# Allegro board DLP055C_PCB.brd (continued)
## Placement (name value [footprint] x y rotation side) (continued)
TP150  TP_WHT  [TP_KEYSTONE_5011]  133.67 69.22 0 top
TP151  TP_WHT  [TP_KEYSTONE_5011]  129.22 69.22 0 top
TP153  TP_WHT  [TP_KEYSTONE_5011]  124.14 55.25 0 top
TP154  TP_WHT  [TP_KEYSTONE_5011]  127.95 55.25 0 top
TP155  TP_WHT  [TP_KEYSTONE_5011]  136.84 66.04 0 top
TP156  TP_WHT  [TP_KEYSTONE_5011]  125.41 69.22 0 top
TP159  TP,28mil Drill,48mil Pad  [HTP-48RD28]  174.31 84.45 0 top
TP163  TP_WHT  [TP_KEYSTONE_5011]  106.36 61.59 0 top
TP164  TP_WHT  [TP_KEYSTONE_5011]  106.36 66.04 270 top
TP165  TP_WHT  [TP_KEYSTONE_5011]  112.87 61.45 270 top
TP166  TP_WHT  [TP_KEYSTONE_5011]  117.16 61.59 270 top
TP167  TP_WHT  [TP_KEYSTONE_5011]  104.14 73.34 270 top
TP168  TP_WHT  [TP_KEYSTONE_5011]  121.6 61.59 270 top
TP169  TP_WHT  [TP_KEYSTONE_5011]  106.05 69.85 0 top
TP170  TP_WHT  [TP_KEYSTONE_5011]  113.98 74.93 270 top
TP208  TP_WHT  [TP_KEYSTONE_5011]  119.06 34.29 0 top
TP209  HDR,1P,1R  [HDR1]  142.56 31.75 0 top
TP210  TP_WHT  [TP_KEYSTONE_5011]  137.48 38.73 0 top
TP211  HDR,1P,1R  [HDR1]  148.91 31.75 0 top
TP212  TP,28mil Drill,48mil Pad  [HTP-48RD28]  115.89 20.95 0 top
TP213  TP,28mil Drill,48mil Pad  [HTP-48RD28]  68.9 10.79 0 top
TP214  TP,28mil Drill,48mil Pad  [HTP-48RD28]  73.34 10.79 0 top
TP215  TP,28mil Drill,48mil Pad  [HTP-48RD28]  46.04 10.16 0 top
TP216  TP,28mil Drill,48mil Pad  [HTP-48RD28]  47.94 10.16 0 top
TP217  TP,20mil PAD  [20MIL_PAD]  146.69 60.96 0 top
TP218  TP,28mil Drill,48mil Pad  [HTP-48RD28]  110.81 73.98 0 top
TP219  TP,28mil Drill,48mil Pad  [HTP-48RD28]  148.27 63.5 0 top
TP220  TP,28mil Drill,48mil Pad  [HTP-48RD28]  152.72 62.86 0 top
TP227  Testpoint_via  [TP-30RD12]  91.36 43.42 270 top
TP228  Testpoint_via  [TP-30RD12]  74.77 59.01 270 top
TP229  Testpoint_via  [TP-30RD12]  87.3 55.46 270 top
TP230  Testpoint_via  [TP-30RD12]  75.36 64.12 270 top
TP231  Testpoint_via  [TP-30RD12]  86.91 65.01 0 top
TP232  Testpoint_via  [TP-30RD12]  83.1 33.89 0 top
TP233  Testpoint_via  [TP-30RD12]  52.86 85.56 180 top
TP234  Testpoint_via  [TP-30RD12]  70.96 51.01 270 top
TP235  Testpoint_via  [TP-30RD12]  63.55 70.21 0 top
TP236  Testpoint_via  [TP-30RD12]  60.64 60.96 0 top
TP237  Testpoint_via  [TP-30RD12]  72.46 64.25 180 top
TP238  Testpoint_via  [TP-30RD12]  73.98 63.5 0 top
TP239  Testpoint_via  [TP-30RD12]  77.21 64.8 180 top
TP240  Testpoint_via  [TP-30RD12]  62.55 64.77 0 top
TP241  Testpoint_via  [TP-30RD12]  55.56 63.5 0 top
TP242  Testpoint_via  [TP-30RD12]  12.38 52.07 0 top
TP243  Testpoint_via  [TP-30RD12]  50.48 93.34 0 top
TP244  Testpoint_via  [TP-30RD12]  52.27 133.38 0 top
TP245  Testpoint_via  [TP-30RD12]  66.99 119.38 0 top
TP246  Testpoint_via  [TP-30RD12]  61.91 132.08 0 top
TP247  Testpoint_via  [TP-30RD12]  77.69 139.93 0 top
TP248  Testpoint_via  [TP-30RD12]  167.96 133.98 0 top
TP249  Testpoint_via  [TP-30RD12]  49.6 35.65 0 top
TP263  Testpoint  [TP-48RD28]  167.96 17.14 180 top
TP264  Testpoint  [TP-48RD28]  177.72 30.08 180 top
TP265  TP,20mil PAD  [20MIL_PAD]  28.26 127 90 top
TP266  TP,20mil PAD  [20MIL_PAD]  26.35 127 90 top
TP267  TP,20mil PAD  [20MIL_PAD]  24.45 127 90 top
TP268  TP_WHT  [TP_KEYSTONE_5011]  180.66 12.7 0 top
TP269  TP_WHT  [TP_KEYSTONE_5011]  171.77 14.61 0 top
TP270  TP_WHT  [TP_KEYSTONE_5011]  176.21 14.61 0 top
TP271  TP_WHT  [TP_KEYSTONE_5011]  184.47 10.16 0 top
TP272  Testpoint_via  [TP-30RD12]  45.64 59.93 0 top
TP273  Testpoint_via  [TP-30RD12]  41.4 49.64 0 top
TP274  Testpoint_via  [TP-30RD12]  44.13 48.89 0 top
TP275  Testpoint_via  [TP-30RD12]  44.13 46.35 0 top
TP276  Testpoint_via  [TP-30RD12]  12.38 53.97 0 top
TP277  Testpoint_via  [TP-30RD12]  51.75 91.44 0 top
TP278  Testpoint_via  [TP-30RD12]  128.37 119.85 0 top
TP279  Testpoint_via  [TP-30RD12]  131.13 131.44 0 top
TP280  Testpoint_via  [TP-30RD12]  103.19 123.83 0 top
TP281  Testpoint_via  [TP-30RD12]  94.3 123.19 0 top
TP282  Testpoint_via  [TP-30RD12]  152.63 112.13 0 top
TP283  Testpoint_via  [TP-30RD12]  131.76 105.41 0 top
TP284  TP,28mil Drill,48mil Pad  [HTP-48RD28]  174.62 95.39 90 top
TP285  TP,28mil Drill,48mil Pad  [HTP-48RD28]  178.48 75.24 90 top
TP286  TP,28mil Drill,48mil Pad  [HTP-48RD28]  85.24 144.84 90 top
U1  TPD2E2U06DRL  [SOT-5_DRL_R-PDSO-N5]  82.23 143.51 90 top
U2  74AHC1G32  [SOIC5-SOT-23_DBV-TI]  63.82 138.11 90 top
U3  74AHC1G08  [SOIC5-SOT-23_DBV-TI]  73.66 138.11 90 top
U4  MT28EW128ABA1HJS-0SIT  [SOIC56-TSOP_SPANSION]  152.08 138.43 180 top
U7  TPS2501DRCR  [TI_DRC0010J_VSON-10]  87.46 125.89 0 top
U8  MT28EW128ABA1HJS-0SIT  [SOIC56-TSOP_SPANSION]  152.08 120.33 180 top
U9  TSOP34838  [SOIC5-SOT-23_DBV-TI]  174.31 26.67 0 bottom
U11  SN74LVC1G17DBVR  [SOIC5-SOT-23_DBV-TI]  167.32 19.68 270 bottom
U12  SN74AUP1G07DCK  [U_5_DCK]  177.8 90.8 180 top
U13  SN74AUP1G07DCK  [U_5_DCK]  90.49 28.89 90 top
U14  SN74AUP1G06DCK  [U_5_DCK]  96.52 39.05 90 top
U15  TIDLP,DLPC7540  [DLPC7540_HBGA676_3131]  151.45 88.9 90 top
U16  SN74AUP1G07DCK  [U_5_DCK]  177.8 86.36 180 top
U17  TPD2E001DRY  [SOIC6-DRY_TI]  11.11 93.98 270 top
U18  SN74AUP1G07DCK  [U_5_DCK]  84.14 29.21 90 top
U19  SN74AUP1G06DCK  [U_5_DCK]  96.52 34.92 90 top
U20  SN74AUP1G07DCK  [U_5_DCK]  96.52 30.8 90 top
U26  MSP430F5529IPN  [PQFP80-PN_TI]  25.72 116.2 180 top
U27  TXS0102  [VSSOP-8_DCU]  37.78 73.03 270 top
U30  AT24C64D-SSHM-T  [SOIC8]  105.73 50.16 0 top
U32  TPS56C230  [20VQFN-HR_RJE]  160.99 53.97 0 top
U33  SN74LVC1G06DBVR  [SOIC5-SOT-23_DBV-TI]  165.12 50.48 270 top
U34  TXS0102  [VSSOP-8_DCU]  172.4 44.77 270 top
U35  DRV8847  [16HTSSOP_PWP0016C]  148.27 43.5 180 top
U36  TXS0102  [VSSOP-8_DCU]  120.33 4.45 180 bottom
U37  TXS0102  [VSSOP-8_DCU]  123.51 4.45 180 bottom
U38  SN74AHC1G125DBVR  [SOIC5-SOT-23_DBV-TI]  71.44 13.97 0 top
U39  SN74LVC1G07DBVR  [SOIC5-SOT-23_DBV-TI]  77.79 13.97 0 top
U40  SN74AUP1G07DCK  [U_5_DCK]  43.81 87.63 270 top
U42  SN74AUP1G07DCK  [U_5_DCK]  44.13 91.44 270 top
U43  SN74LVC827APWR  [SOIC24-PW_TI]  129.86 61.59 180 top
U46  MAX3232CPWR  [SOIC16-PW_TI]  15.88 31.75 90 top
U47  TSOP34838  [SOIC5-SOT-23_DBV-TI]  141.29 57.78 270 top
U48  SN74LVC1G06DBVR  [SOIC5-SOT-23_DBV-TI]  101.28 66.04 270 bottom
U49  SN74LVC827APWR  [SOIC24-PW_TI]  113.35 67.94 180 top
U51  74LVTH16244  [SOIC48-DGG_TI]  127.95 34.92 0 top
U53  TSOP34838  [IR3-TSOP34_VIS]  115.25 85.09 0 top
U54  TSOP34838  [IR3-TSOP34_VIS]  105.73 85.09 0 top
U55  74AHC1G32  [SOIC5-SOT-23_DBV-TI]  137.48 33.66 0 top
U58  SN74LVC1G17DBVR  [SOIC5-DBV_TI]  81.6 107.95 90 bottom
U59  TPS259260DRCR  [SOIC10-DRC_TI]  62.55 123.83 180 bottom
U500  38MHz  [SIT1602BC-13-2520_CTS_SITIME]  131.13 93.34 270 bottom
U501  TPD2E2U06DRL  [SOT-5_DRL_R-PDSO-N5]  19.37 76.83 90 top
U502  40MHz  [OSC4-KC2520B_KYO]  180.02 94.61 180 bottom
U503  CDCLVC1102PW  [SOIC8-PW_TI]  176.21 90.8 270 bottom
U519  N-CHANNEL MOSFET  [SOT323_DIODESINC]  77.15 143.51 180 top
U520  SN74LVC1G07  [SOIC5-SOT-23_DBV-TI]  77.15 144.14 180 bottom
U521  TPS259241  [SOIC10-DRC_TI]  63.18 127 90 top
U522  CSD17579  [SOIC8-Q5_TI]  68.9 132.08 0 top
U523  N-CHANNEL MOSFET  [SOT23AVX]  83.38 91.44 90 bottom
U524  TPS54327  [SOIC8-DDA-A_TI]  166.05 140.34 180 bottom
U525  LM3881  [SOIC8-DGK_TI]  87.31 96.52 270 top
U526  LM3881  [SOIC8-DGK_TI]  84.77 91.44 270 top
U527  N-CHANNEL MOSFET  [SOT23AVX]  91.12 90.8 90 top
U528  N-CHANNEL MOSFET  [SOT23AVX]  91.12 90.17 180 bottom
U529  SN74LVC1G07  [SOIC5-SOT-23_DBV-TI]  86.04 109.86 270 bottom
U538  LM393  [SOIC8-PW_TI]  126.05 121.92 0 bottom
U539  LM393  [SOIC8-PW_TI]  134.3 109.86 90 bottom
U555  (MOTOR DRIVE)  [QF48_PPAD-A]  67.63 59.05 0 top
U556  (MOTOR DRIVE)  [QF48_PPAD-A]  28.26 51.44 0 top
U557  (MOTOR DRIVE)  [QF48_PPAD-A]  76.52 100.97 0 top
U558  SN74AUP1G07DCK  [U_5_DCK]  25.32 116.44 90 bottom
U559  TXS0102  [VSSOP-8_DCU]  16.83 100.97 0 top
U560  M24C64-WMN6TP  [SOIC8-D_TI]  37.78 78.11 90 top
U561  TXS0102  [VSSOP-8_DCU]  36.51 83.82 90 top
U562  CY7C65215A-32LTXI  [QFN32-5X5-A_CYP]  25.08 78.11 270 top
U563  SN74AUP1G06DCK  [U_5_DCK]  31.43 80.64 90 top
U564  SN74AUP1G06DCK  [U_5_DCK]  44.13 83.82 270 top
U565  74AHC1G32  [SOIC5-SOT-23_DBV-TI]  60.01 146.05 0 top
U566  LM393  [SOIC8-PW_TI]  98.74 119.38 180 bottom
U567  TSOP34838  [SOIC5-SOT-23_DBV-TI]  179.39 26.04 0 bottom
U568  SN74LVC1G07  [SOIC5-SOT-23_DBV-TI]  65.5 147.79 180 bottom
U569  SN74LVC1G07  [SOIC5-SOT-23_DBV-TI]  69.41 147.76 180 bottom
VR1  20K  [POT-3314G]  127.32 127.64 0 top
VR2  20K  [POT-3314G]  98.74 127 270 top
VR3  20K  [POT-3314G]  134.94 109.86 270 top
X1  40 MHz  [TXC_TM3225]  172.72 92.39 270 top
X2  38 MHz  [TXC_TM3225]  131.44 88.27 90 bottom

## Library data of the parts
C1 C2 C5-C8 C10 C15 C27 C34 C71 C74 C91 C95-C97 C108-C110 C126 C127 C130 C133 C136 C137 C141 C147 C161 C170 C172 C202 C240 C242 C259 C557 C576 C583 C668 C669 C677-C679 C697-C699 = PAS,CAP,NP
C14 C69 C70 C124 C125 C134 C135 C138 C148-C160 C162-C169 C171 C173-C201 C203-C239 C241 C243-C258 C260-C269 C275-C291 C298-C304 C317 C320 C321 C502-C504 C507 C508 C511 C514 C515 C517 C528-C530 C547 C548 C622-C625 C654 C664-C667 C670 C675 C676 C682-C684 C687-C696 C700 C830 C837 = PAS,CAP,NP: alternate symbols: (0402_1mm)
C18 C60 C752-C759 C762-C801 C806-C808 C810-C820 C827-C829 C831-C836 = C
C49-C54 C61-C68 C72 C73 = CER 0.1UF 16V 10% X5R 0402: alternate symbols: (0402_1mm); signal model: CER_0.1UF_16V_10%_X5R_0402_0402_100nF
C58 C59 C760 C761 C802-C805 C821-C826 = CAPACITOR_POL
C519-C521 C531 C549 C585 = CER 0.1UF 16V 10% X5R 0402: alternate symbols: (0402_1mm)
C809 = CAP NP: alternate symbols: (0603)
D1 D5-D8 D10 D15 D52 D53 = PAS,DIODE,LED,ALT
D30 D32 D35-D48 = Schottky_Diode
D49 D51 = PAS,DIODE,ZENOR,SOT-23,Ap1,Cp3
D50 = PWR,REF,LMV431A,SOT-23
DN1-DN12 = DS_DUAL_S_AJK
F1 = PAS,FERRITE BEAD,3
FB1-FB4 = Ferrite Bead_1
J2 = EM,CONN,USB,TYPE-AB
J3 J7 J10 = TMP_154138
J4 J5 J8 J11 J62 = EM,HDR,2P,1R,1x,B2B_EH,inline
J6 = EM,HDR,10P,1R
J9 J26 J52-J57 J60 J61 J67 J68 J72 J84 J94 J95 J98 J530 = EM,JMP,2P,1R
J12 J16 J536 = EM,HDR,4P,1R,1x,picoblade
J14 J15 = HDR_2: alternate symbols: (HDR2_2MM)
J17 = EM,CONN,12P+2G,1R,FLEX,1x
J20 J21 J27 = EM,HDR,6P,1R
J22 J23 J45 J103-J105 J506 = EM,HDR,6P,1R,1x,B6B-EH
J28 J115 = EM,HDR,12P,1R
J42 J44 J500 = EM,CONN,51P,FI-RE51S,VF and HF
J43 J69 J110 = EM,HDR,14P,1R
J51 = EM,CONN,4P,EH,Devasys,1x
J64 J76 J78 J82 J86 J87 J89 J106 J502 J505 = EM,JMP,3P,1R,1X,ALT
J70 = EM,HDR,14P,2R,1X,Narrow
J73 J503 = EM,HDR,4P,1R,1x,B4B-EH
J74 = EM,HDR,4P,1R,1x,NARROW
J75 = EM,JMP,10P,2R,1x
J77 J79 J88 J90 = EM,JMP,1P,1R,2
J83 = EM,CONN,USB,TYPE-B
J85 = EM,HDR,3P,1R,1x,B3B-EH
J96 = EM,HDR,12P,1R,1x
J97 = EM,HDR,22P,2R
J102 = EM,CONN,DB9,ALT
J111-J113 = EM,HDR,6P,2R,1x
J114 = EM,HDR,3P,1R
J120 J121 = EM,HDR,12P,1R,1x,B12B-EH
J122 = EM,HDR,7P,1R,1x,B7B-EH
J501 = EM,HDR,20P,2R,NARROW_SYM
J515 J519 J523 = CON4_0
J516-J518 J520-J522 J524-J526 = 2pin
J527 J528 = EM,HDR,2P,1R,2x
J529 = PJ-002AH_0
J532 J533 J535 = CON3_0
L2 L11 = PAS,INDUCTOR
L13-L24 L505 L506 = PAS,INDUCTOR: alternate symbols: (0402_1mm)
L515-L531 = L
Q1 = ANA,TRANSISTOR,2N2222A,SOT-23
Q6 = ANA,MOSFET,N-CH,E,3PICOSTAR_0
Q10 = NTD14NO3RT4_1
Q11 = NTD14N03RT4G_CUS
Q12 = ANA,MOSFET,P-CH,E,SOT223
Q13 = ANA,MOSFET,N-CH,E,2N7002,SOT-23
R1 R2 R8-R11 R13 R14 R18-R22 R29-R31 R34 R36 R38-R40 R43 R51-R53 R55-R57 R61 R63 R64 R73 R75-R79 R81-R83 R87 R88 R90 R91 R95-R97 R99-R101 R103-R106 R109-R114 R116-R125 R127 R128 R133-R151 R153-R157 R168 R169 R200 R201 R209-R212 R217 R219 R222 R234 R235 R237 R256-R261 R504-R508 R511 R517 R519 R520 R522-R526 R528 R529 R533-R540 R542-R550 R581 R585 R586 R589 R590 R592-R599 R601 R604-R615 R623 R626-R629 R632 R635 R640 R642-R656 R660-R680 R706 R710-R717 R853-R855 R859-R871 R884-R887 = PAS,R,large: alternate symbols: (0402_1mm)
R4 R5 = PAS,R,large: signal model: PAS_R_LARGE_0402_27.4__27.4
R32 R37 R42 R54 R62 R65 R66 R80 R84-R86 R89 R92-R94 R98 R102 R152 R218 R226 R246 R856-R858 = PAS,R,large
R108 R175 R176 R179 R181 R184 R193 R195-R198 R739 R740 R742 R744 R747 R750-R752 R754-R756 R758 R759 R763-R821 R827 R828 R830 R832-R834 R836 R838 R840-R852 R872-R883 = R
R822-R826 R829 R839 = PAS,R
R831 R835 R837 = R: alternate symbols: (0402-1MM)
SW1 SW3 = EM,SW,SPDT,GT11,1x
SW5 = SW SPST_1: alternate symbols: (SW5_GT12MSCBE)
TP1-TP3 TP5-TP9 TP11 TP12 TP14 TP20-TP24 TP38-TP40 TP46-TP56 TP78-TP89 TP106-TP109 TP129-TP141 TP144-TP151 TP153-TP156 TP159 TP163-TP170 TP208-TP220 TP268-TP271 TP284-TP286 = EM,TERM,TESTPOINT
TP32-TP37 TP41-TP43 TP64-TP77 TP111-TP128 TP265-TP267 = BF,HOLE,PLATED,TESTPIN
TP227-TP249 TP272-TP283 = Testpoint
TP263 TP264 = EM,TERM,TESTPOINT: alternate symbols: (TP-48RD28)
U1 U501 = PAS,DIODE,TVS,TPD2E2U06DRL,1x
U2 U55 U565 = LOG,OR,Tiny Logic,small
U3 = LOG,AND,Tiny Logic,Small
U4 U8 = MEM,FLASH,256Mb,x16,TSOP-56
U7 = PWR,SW,TPS2501,USB
U9 U38 U47 U567 = LOG,BUF,74LVC1G125,1x
U11 = LOG,BUF,SCHMITT_TRIG,1G17_7
U12 = TMP_18
U13 = TMP_21
U14 = TMP_22
U15 = TIDLP,DLPC7540
U16 = TMP_4
U17 = PAS,DIODE,TVS,TPD2E001DRY,1x
U18 = TMP_20
U19 = TMP_19
U20 = TMP_23
U26 = PROC,MICCNTL,1x,MSP430F5529IPN
U27 U34 U36 U37 U559 U561 = INF,DRVR,I2C,TXS0102,1x
U30 = MEM,EEPROM,24LCxx,ALT
U32 = PWR,REG,TPS56C230,1X
U33 = TMP_24
U35 = ANA,DRV,DRV8447,1x_3
U39 = TMP_30
U40 = TMP_27
U42 = TMP_28
U43 U49 = LOG,BUF,74X827A
U46 = INF,DRVR,RS232,MAX3232E
U48 = TMP_31
U51 = LOG,BUF,74x16244
U53 U54 = ANA,LIGHTSENSOR,IR_RECVR
U58 = LOG,BUF,SCHMITT_TRIG,1G17_8
U59 = TPS259260
U500 U502 = ANA,OSC,4P,1X,small
U503 = INF,CLK DRVR,CDCLVC1102
U519 U523 U527 U528 = N-FET
U520 U568 U569 = TMP_33
U521 = TPS259240_0
U522 = CSD17579
U524 = TPS54327_0
U525 U526 = LM3881
U529 = TMP_32
U538 U539 U566 = OPAMP_DUAL
U555 = PMD1000_2
U556 U557 = PMD1000_3
U558 = TMP_29
U560 = MEM,EEPROM,24LCxx
U562 = INF,USB2SERIAL,CY7C65215,1x
U563 = TMP_25
U564 = TMP_26
VR1-VR3 = POT_R_S
X1 = 7V-40.000MDDE-T_CUS
X2 = 7V-38.000MAAV-T_CUS

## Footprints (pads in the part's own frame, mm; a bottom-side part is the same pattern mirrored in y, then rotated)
3-PICOSTAR_3-XFDFN
  rect 0.222x0.35 smd: 1(-0.175,-0.325) 2(0.175,-0.325)
  rect 0.6x0.35 smd: 3(0,0.325)
16HTSSOP_PWP0016C
  rect 1.5x0.45 smd: 1(-2.9,2.275) 2(-2.9,1.625) 3(-2.9,0.975) 4(-2.9,0.325) 5(-2.9,-0.325) 6(-2.9,-0.975) 7(-2.9,-1.625) 8(-2.9,-2.275) 9(2.9,-2.275) 10(2.9,-1.625) 11(2.9,-0.975) 12(2.9,-0.325) 13(2.9,0.325) 14(2.9,0.975) 15(2.9,1.625) 16(2.9,2.275)
  rect 2.46x2.31 smd: 17(0,0)
20MIL_PAD
  round 0.508 smd: 1(0,0)
20VQFN-HR_RJE
  rect 0.6x0.2 smd: 1(-1.4,0.9) 2(-1.4,0.45) 3(-1.4,0) 4(-1.4,-0.45) 5(-1.4,-0.9) 11(1.4,-0.9) 12(1.4,-0.45) 13(1.4,0) 14(1.4,0.45) 15(1.4,0.9)
  rect 0.2x0.6 smd: 6(-0.9,-1.4) 7(-0.45,-1.4) 8(0,-1.4) 9(0.45,-1.4) 10(0.9,-1.4) 16(0.9,1.4) 17(0.45,1.4) 18(0,1.4) 19(-0.45,1.4) 20(-0.9,1.4)
  rect 0.926x0.975 smd: 21(0.123,-0.007)
35F0121-1SR-10_LAIRD
  rect 2.769x1.473 smd: 1(-4.013,0) 2(4.013,0)
0201
  rect 0.356x0.305 smd: 1(-0.305,0) 2(0.305,0)
0402
  rect 0.5x0.5 smd: 1(-0.521,0) 2(0.521,0)
0603
  rect 0.762x1.016 smd: 1(0.838,0) 2(-0.838,0)
0805
  rect 1.295x1.499 smd: 1(-0.95,0) 2(0.95,0)
0805WIDE-KRL2012E_SUSUMU
  rect 2.311x0.787 smd: 1(0,0.61) 2(0,-0.61)
1206
  rect 1.6x1.6 smd: 1(-1.397,0) 2(1.397,0)
1210
  rect 0.9x2.3 smd: 1(-1.55,0) 2(1.55,0)
7343
  rect 2.591x2.388 smd: 1(-3.2,0) 2(3.2,0)
COILCRAFT_LPS4018
  rect 1.905x4.572 smd: 1(-1.587,0) 2(1.587,0)
CONN2-B2B-EH_JST
  rect 1.575x1.575 hole 1.067: 1(0,0)
  round 1.575 hole 1.067: 2(2.489,0)
CONN3-53398-A_MOLEX
  rect 2.108x2.997 smd: (-3.8,-2.913) (3.8,-2.913)
  rect 0.61x1.6 smd: 1(-1.25,0) 2(0,0) 3(1.25,0)
CONN3-B3B-EH_JST
  rect 1.575x1.575 hole 1.067: 1(0,0)
  round 1.575 hole 1.067: 2(-2.489,0) 3(-4.978,0)
CONN4-52808_MOLEX
  rect 0.61x1.448 smd: 1(-1.501,-1.778) 3(0.5,-1.778)
  rect 0.61x1.651 smd: 2(-0.5,1.778) 4(1.501,1.778)
CONN4-53398_MOLEX
  rect 2.1x3 smd: (-4.425,-2.75) (4.425,-2.75)
  rect 0.8x1.3 smd: 1(-1.875,0) 2(-0.625,0) 3(0.625,0) 4(1.875,0)
CONN4-S4BEH_JST
  rect 1.575x1.575 hole 1.067: 1(0,0)
  round 1.575 hole 1.067: 2(2.489,0) 3(4.978,0) 4(7.468,0)
CONN4-USB-897-43-004-90_MILL
  round 1.422 hole 0.914: 1(0,0) 2(-2.5,0) 3(-2.5,-2) 4(0,-2)
  round 3.175 hole 2.286: 5(4.77,-4.71) 6(-7.27,-4.71)
CONN6-53398-0690_MOLEX
  rect 2.108x2.997 smd: (-5.675,-1.85) (5.675,-1.85)
  rect 0.61x1.6 smd: 1(-3.125,1.063) 2(-1.875,1.063) 3(-0.625,1.063) 4(0.625,1.063) 5(1.875,1.063) 6(3.125,1.063)
CONN9-190-009-A_NORCOMP_REV
  round 4.216 hole 3.2: (-12.495,-0.65) (12.495,-0.65)
  round 0.762 hole 1.499 unplated: (-7.95,-0.65) (7.95,-0.65)
  rect 0.787x3.708 smd: 1(-5.54,0) 2(-2.77,0) 3(0,0) 4(2.77,0) 5(5.54,0) 6(-4.155,0) 7(-1.385,0) 8(1.385,0) 9(4.155,0)
CONN12-53398_MOLEX
  rect 2.108x2.997 smd: (-9.425,-1.85) (9.425,-1.85)
  rect 0.61x1.6 smd: 1(-6.875,1.063) 2(-5.625,1.063) 3(-4.375,1.063) 4(-3.125,1.063) 5(-1.875,1.063) 6(-0.625,1.063) 7(0.625,1.063) 8(1.875,1.063) 9(3.125,1.063) 10(4.375,1.063) 11(5.625,1.063) 12(6.875,1.063)
CONN12-FH12_HRS
  rect 1.854x2.184 smd: (-4.5,-2.895) (4.5,-2.895)
  rect 0.254x1.016 smd: 1(-2.75,0) 2(-2.25,0) 3(-1.75,0) 4(-1.25,0) 5(-0.75,0) 6(-0.25,0) 7(0.25,0) 8(0.75,0) 9(1.25,0) 10(1.75,0) 11(2.25,0) 12(2.75,0)
CONN14-XF2M-REV-A_OMRON
  rect 1.905x1.524 smd: (-5.201,-3.987) (5.201,-3.987)
  rect 0.254x1.295 smd: 1(3.25,0) 2(2.75,0) 3(2.25,0) 4(1.75,0) 5(1.25,0) 6(0.75,0) 7(0.25,0) 8(-0.25,0) 9(-0.75,0) 10(-1.25,0) 11(-1.75,0) 12(-2.25,0) 13(-2.75,0) 14(-3.25,0)
CONN22-B22B-PHD_JST
  rect 1.473x1.473 hole 0.965: 1(0,0)
  round 1.473 hole 0.965: 2(2,0) 3(0,2) 4(2,2) 5(0,4) 6(2,4) 7(0,6) 8(2,6) 9(0,8) 10(2,8) 11(0,10) 12(2,10) 13(0,12) 14(2,12) 15(0,14) 16(2,14) 17(0,16) 18(2,16) 19(0,18) 20(2,18) 21(0,20) 22(2,20)
DIO-SMA_DIO-MOD
  rect 2.489x1.702 smd: 1(-2.007,0) 2(2.007,0)
DLPC7540_HBGA676_3131
  round 0.457 smd: A1(-14.5,14.5) A2(-13.5,14.5) A3(-12.5,14.5) A4(-11.5,14.5) A5(-10.5,14.5) A6(-9.5,14.5) A7(-8.5,14.5) A8(-7.5,14.5) A9(-6.5,14.5) A10(-5.5,14.5) A11(-4.5,14.5) A12(-3.5,14.5) A13(-2.5,14.5) A14(-1.5,14.5) A15(-0.5,14.5) A16(0.5,14.5) A17(1.5,14.5) A18(2.5,14.5) A19(3.5,14.5) A20(4.5,14.5) A21(5.5,14.5) A22(6.5,14.5) A23(7.5,14.5) A24(8.5,14.5) A25(9.5,14.5) A26(10.5,14.5) A27(11.5,14.5) A28(12.5,14.5) A29(13.5,14.5) A30(14.5,14.5) AA1(-14.5,-5.5) AA2(-13.5,-5.5) AA3(-12.5,-5.5) AA4(-11.5,-5.5) AA5(-10.5,-5.5) AA6(-9.5,-5.5) AA25(9.5,-5.5) AA26(10.5,-5.5) AA27(11.5,-5.5) AA28(12.5,-5.5) AA29(13.5,-5.5) AA30(14.5,-5.5) AB1(-14.5,-6.5) AB2(-13.5,-6.5) AB3(-12.5,-6.5) AB4(-11.5,-6.5) AB5(-10.5,-6.5) AB6(-9.5,-6.5) AB25(9.5,-6.5) AB26(10.5,-6.5) AB27(11.5,-6.5) AB28(12.5,-6.5) AB29(13.5,-6.5) AB30(14.5,-6.5) AC1(-14.5,-7.5) AC2(-13.5,-7.5) AC3(-12.5,-7.5) AC4(-11.5,-7.5) AC5(-10.5,-7.5) AC6(-9.5,-7.5) AC25(9.5,-7.5) AC26(10.5,-7.5) AC27(11.5,-7.5) AC28(12.5,-7.5) AC29(13.5,-7.5) AC30(14.5,-7.5) AD1(-14.5,-8.5) AD2(-13.5,-8.5) AD3(-12.5,-8.5) AD4(-11.5,-8.5) AD5(-10.5,-8.5) AD6(-9.5,-8.5) AD25(9.5,-8.5) AD26(10.5,-8.5) AD27(11.5,-8.5) AD28(12.5,-8.5) AD29(13.5,-8.5) AD30(14.5,-8.5) AE1(-14.5,-9.5) AE2(-13.5,-9.5) AE3(-12.5,-9.5) AE4(-11.5,-9.5) AE5(-10.5,-9.5) AE6(-9.5,-9.5) AE7(-8.5,-9.5) AE8(-7.5,-9.5) AE9(-6.5,-9.5) AE10(-5.5,-9.5) AE11(-4.5,-9.5) AE12(-3.5,-9.5) AE13(-2.5,-9.5) AE14(-1.5,-9.5) AE15(-0.5,-9.5) AE16(0.5,-9.5) AE17(1.5,-9.5) AE18(2.5,-9.5) AE19(3.5,-9.5) AE20(4.5,-9.5) AE21(5.5,-9.5) AE22(6.5,-9.5) AE23(7.5,-9.5) AE24(8.5,-9.5) AE25(9.5,-9.5) AE26(10.5,-9.5) AE27(11.5,-9.5) AE28(12.5,-9.5) AE29(13.5,-9.5) AE30(14.5,-9.5) AF1(-14.5,-10.5) AF2(-13.5,-10.5) AF3(-12.5,-10.5) AF4(-11.5,-10.5) AF5(-10.5,-10.5) AF6(-9.5,-10.5) AF7(-8.5,-10.5) AF8(-7.5,-10.5) AF9(-6.5,-10.5) AF10(-5.5,-10.5) AF11(-4.5,-10.5) AF12(-3.5,-10.5) AF13(-2.5,-10.5) AF14(-1.5,-10.5) AF15(-0.5,-10.5) AF16(0.5,-10.5) AF17(1.5,-10.5) AF18(2.5,-10.5) AF19(3.5,-10.5) AF20(4.5,-10.5) AF21(5.5,-10.5) AF22(6.5,-10.5) AF23(7.5,-10.5) AF24(8.5,-10.5) AF25(9.5,-10.5) AF26(10.5,-10.5) AF27(11.5,-10.5) AF28(12.5,-10.5) AF29(13.5,-10.5) AF30(14.5,-10.5) AG1(-14.5,-11.5) AG2(-13.5,-11.5) AG3(-12.5,-11.5) AG4(-11.5,-11.5) AG5(-10.5,-11.5) AG6(-9.5,-11.5) AG7(-8.5,-11.5) AG8(-7.5,-11.5) AG9(-6.5,-11.5) AG10(-5.5,-11.5) AG11(-4.5,-11.5) AG12(-3.5,-11.5) AG13(-2.5,-11.5) AG14(-1.5,-11.5) AG15(-0.5,-11.5) AG16(0.5,-11.5) AG17(1.5,-11.5) AG18(2.5,-11.5) AG19(3.5,-11.5) AG20(4.5,-11.5) AG21(5.5,-11.5) AG22(6.5,-11.5) AG23(7.5,-11.5) AG24(8.5,-11.5) AG25(9.5,-11.5) AG26(10.5,-11.5) AG27(11.5,-11.5) AG28(12.5,-11.5) AG29(13.5,-11.5) AG30(14.5,-11.5) AH1(-14.5,-12.5) AH2(-13.5,-12.5) AH3(-12.5,-12.5) AH4(-11.5,-12.5) AH5(-10.5,-12.5) AH6(-9.5,-12.5) AH7(-8.5,-12.5) AH8(-7.5,-12.5) AH9(-6.5,-12.5) AH10(-5.5,-12.5) AH11(-4.5,-12.5) AH12(-3.5,-12.5) AH13(-2.5,-12.5) AH14(-1.5,-12.5) AH15(-0.5,-12.5) AH16(0.5,-12.5) AH17(1.5,-12.5) AH18(2.5,-12.5) AH19(3.5,-12.5) AH20(4.5,-12.5) AH21(5.5,-12.5) AH22(6.5,-12.5) AH23(7.5,-12.5) AH24(8.5,-12.5) AH25(9.5,-12.5) AH26(10.5,-12.5) AH27(11.5,-12.5) AH28(12.5,-12.5) AH29(13.5,-12.5) AH30(14.5,-12.5) AJ1(-14.5,-13.5) AJ2(-13.5,-13.5) AJ3(-12.5,-13.5) AJ4(-11.5,-13.5) AJ5(-10.5,-13.5) AJ6(-9.5,-13.5) AJ7(-8.5,-13.5) AJ8(-7.5,-13.5) AJ9(-6.5,-13.5) AJ10(-5.5,-13.5) AJ11(-4.5,-13.5) AJ12(-3.5,-13.5) AJ13(-2.5,-13.5) AJ14(-1.5,-13.5) AJ15(-0.5,-13.5) AJ16(0.5,-13.5) AJ17(1.5,-13.5) AJ18(2.5,-13.5) AJ19(3.5,-13.5) AJ20(4.5,-13.5) AJ21(5.5,-13.5) AJ22(6.5,-13.5) AJ23(7.5,-13.5) AJ24(8.5,-13.5) AJ25(9.5,-13.5) AJ26(10.5,-13.5) AJ27(11.5,-13.5) AJ28(12.5,-13.5) AJ29(13.5,-13.5) AJ30(14.5,-13.5) AK1(-14.5,-14.5) AK2(-13.5,-14.5) AK3(-12.5,-14.5) AK4(-11.5,-14.5) AK5(-10.5,-14.5) AK6(-9.5,-14.5) AK7(-8.5,-14.5) AK8(-7.5,-14.5) AK9(-6.5,-14.5) AK10(-5.5,-14.5) AK11(-4.5,-14.5) AK12(-3.5,-14.5) AK13(-2.5,-14.5) AK14(-1.5,-14.5) AK15(-0.5,-14.5) AK16(0.5,-14.5) AK17(1.5,-14.5) AK18(2.5,-14.5) AK19(3.5,-14.5) AK20(4.5,-14.5) AK21(5.5,-14.5) AK22(6.5,-14.5) AK23(7.5,-14.5) AK24(8.5,-14.5) AK25(9.5,-14.5) AK26(10.5,-14.5) AK27(11.5,-14.5) AK28(12.5,-14.5) AK29(13.5,-14.5) AK30(14.5,-14.5) B1(-14.5,13.5) B2(-13.5,13.5) B3(-12.5,13.5) B4(-11.5,13.5) B5(-10.5,13.5) B6(-9.5,13.5) B7(-8.5,13.5) B8(-7.5,13.5) B9(-6.5,13.5) B10(-5.5,13.5) B11(-4.5,13.5) B12(-3.5,13.5) B13(-2.5,13.5) B14(-1.5,13.5) B15(-0.5,13.5) B16(0.5,13.5) B17(1.5,13.5) B18(2.5,13.5) B19(3.5,13.5) B20(4.5,13.5) B21(5.5,13.5) B22(6.5,13.5) B23(7.5,13.5) B24(8.5,13.5) B25(9.5,13.5) B26(10.5,13.5) B27(11.5,13.5) B28(12.5,13.5) B29(13.5,13.5) B30(14.5,13.5) C1(-14.5,12.5) C2(-13.5,12.5) C3(-12.5,12.5) C4(-11.5,12.5) C5(-10.5,12.5) C6(-9.5,12.5) C7(-8.5,12.5) C8(-7.5,12.5) C9(-6.5,12.5) C10(-5.5,12.5) C11(-4.5,12.5) C12(-3.5,12.5) C13(-2.5,12.5) C14(-1.5,12.5) C15(-0.5,12.5) C16(0.5,12.5) C17(1.5,12.5) C18(2.5,12.5) C19(3.5,12.5) C20(4.5,12.5) C21(5.5,12.5) C22(6.5,12.5) C23(7.5,12.5) C24(8.5,12.5) C25(9.5,12.5) C26(10.5,12.5) C27(11.5,12.5) C28(12.5,12.5) C29(13.5,12.5) C30(14.5,12.5) D1(-14.5,11.5) D2(-13.5,11.5) D3(-12.5,11.5) D4(-11.5,11.5) D5(-10.5,11.5) D6(-9.5,11.5) D7(-8.5,11.5) D8(-7.5,11.5) D9(-6.5,11.5) D10(-5.5,11.5) D11(-4.5,11.5) D12(-3.5,11.5) D13(-2.5,11.5) D14(-1.5,11.5) D15(-0.5,11.5) D16(0.5,11.5) D17(1.5,11.5) D18(2.5,11.5) D19(3.5,11.5) D20(4.5,11.5) D21(5.5,11.5) D22(6.5,11.5) D23(7.5,11.5) D24(8.5,11.5) D25(9.5,11.5) D26(10.5,11.5) D27(11.5,11.5) D28(12.5,11.5) D29(13.5,11.5) D30(14.5,11.5) E1(-14.5,10.5) E2(-13.5,10.5) E3(-12.5,10.5) E4(-11.5,10.5) E5(-10.5,10.5) E6(-9.5,10.5) E7(-8.5,10.5) E8(-7.5,10.5) E9(-6.5,10.5) E10(-5.5,10.5) E11(-4.5,10.5) E12(-3.5,10.5) E13(-2.5,10.5) E14(-1.5,10.5) E15(-0.5,10.5) E16(0.5,10.5) E17(1.5,10.5) E18(2.5,10.5) E19(3.5,10.5) E20(4.5,10.5) E21(5.5,10.5) E22(6.5,10.5) E23(7.5,10.5) E24(8.5,10.5) E25(9.5,10.5) E26(10.5,10.5) E27(11.5,10.5) E28(12.5,10.5) E29(13.5,10.5) E30(14.5,10.5) F1(-14.5,9.5) F2(-13.5,9.5) F3(-12.5,9.5) F4(-11.5,9.5) F5(-10.5,9.5) F6(-9.5,9.5) F7(-8.5,9.5) F8(-7.5,9.5) F9(-6.5,9.5) F10(-5.5,9.5) F11(-4.5,9.5) F12(-3.5,9.5) F13(-2.5,9.5) F14(-1.5,9.5) F15(-0.5,9.5) F16(0.5,9.5) F17(1.5,9.5) F18(2.5,9.5) F19(3.5,9.5) F20(4.5,9.5) F21(5.5,9.5) F22(6.5,9.5) F23(7.5,9.5) F24(8.5,9.5) F25(9.5,9.5) F26(10.5,9.5) F27(11.5,9.5) F28(12.5,9.5) F29(13.5,9.5) F30(14.5,9.5) G1(-14.5,8.5) G2(-13.5,8.5) G3(-12.5,8.5) G4(-11.5,8.5) G5(-10.5,8.5) G6(-9.5,8.5) G25(9.5,8.5) G26(10.5,8.5) G27(11.5,8.5) G28(12.5,8.5) G29(13.5,8.5) G30(14.5,8.5) H1(-14.5,7.5) H2(-13.5,7.5) H3(-12.5,7.5) H4(-11.5,7.5) H5(-10.5,7.5) H6(-9.5,7.5) H25(9.5,7.5) H26(10.5,7.5) H27(11.5,7.5) H28(12.5,7.5) H29(13.5,7.5) H30(14.5,7.5) J1(-14.5,6.5) J2(-13.5,6.5) J3(-12.5,6.5) J4(-11.5,6.5) J5(-10.5,6.5) J6(-9.5,6.5) J25(9.5,6.5) J26(10.5,6.5) J27(11.5,6.5) J28(12.5,6.5) J29(13.5,6.5) J30(14.5,6.5) K1(-14.5,5.5) K2(-13.5,5.5) K3(-12.5,5.5) K4(-11.5,5.5) K5(-10.5,5.5) K6(-9.5,5.5) K25(9.5,5.5) K26(10.5,5.5) K27(11.5,5.5) K28(12.5,5.5) K29(13.5,5.5) K30(14.5,5.5) L1(-14.5,4.5) L2(-13.5,4.5) L3(-12.5,4.5) L4(-11.5,4.5) L5(-10.5,4.5) L6(-9.5,4.5) L11(-4.5,4.5) L12(-3.5,4.5) L13(-2.5,4.5) L14(-1.5,4.5) L15(-0.5,4.5) L16(0.5,4.5) L17(1.5,4.5) L18(2.5,4.5) L19(3.5,4.5) L20(4.5,4.5) L25(9.5,4.5) L26(10.5,4.5) L27(11.5,4.5) L28(12.5,4.5) L29(13.5,4.5) L30(14.5,4.5) M1(-14.5,3.5) M2(-13.5,3.5) M3(-12.5,3.5) M4(-11.5,3.5) M5(-10.5,3.5) M6(-9.5,3.5) M11(-4.5,3.5) M12(-3.5,3.5) M13(-2.5,3.5) M14(-1.5,3.5) M15(-0.5,3.5) M16(0.5,3.5) M17(1.5,3.5) M18(2.5,3.5) M19(3.5,3.5) M20(4.5,3.5) M25(9.5,3.5) M26(10.5,3.5) M27(11.5,3.5) M28(12.5,3.5) M29(13.5,3.5) M30(14.5,3.5) N1(-14.5,2.5) N2(-13.5,2.5) N3(-12.5,2.5) N4(-11.5,2.5) N5(-10.5,2.5) N6(-9.5,2.5) N11(-4.5,2.5) N12(-3.5,2.5) N13(-2.5,2.5) N14(-1.5,2.5) N15(-0.5,2.5) N16(0.5,2.5) N17(1.5,2.5) N18(2.5,2.5) N19(3.5,2.5) N20(4.5,2.5) N25(9.5,2.5) N26(10.5,2.5) N27(11.5,2.5) N28(12.5,2.5) N29(13.5,2.5) N30(14.5,2.5) P1(-14.5,1.5) P2(-13.5,1.5) P3(-12.5,1.5) P4(-11.5,1.5) P5(-10.5,1.5) P6(-9.5,1.5) P11(-4.5,1.5) P12(-3.5,1.5) P13(-2.5,1.5) P14(-1.5,1.5) P15(-0.5,1.5) P16(0.5,1.5) P17(1.5,1.5) P18(2.5,1.5) P19(3.5,1.5) P20(4.5,1.5) P25(9.5,1.5) P26(10.5,1.5) P27(11.5,1.5) P28(12.5,1.5) P29(13.5,1.5) P30(14.5,1.5) R1(-14.5,0.5) R2(-13.5,0.5) R3(-12.5,0.5) R4(-11.5,0.5) R5(-10.5,0.5) R6(-9.5,0.5) R11(-4.5,0.5) R12(-3.5,0.5) R13(-2.5,0.5) R14(-1.5,0.5) R15(-0.5,0.5) R16(0.5,0.5) R17(1.5,0.5) R18(2.5,0.5) R19(3.5,0.5) R20(4.5,0.5) R25(9.5,0.5) R26(10.5,0.5) R27(11.5,0.5) R28(12.5,0.5) R29(13.5,0.5) R30(14.5,0.5) T1(-14.5,-0.5) T2(-13.5,-0.5) T3(-12.5,-0.5) T4(-11.5,-0.5) T5(-10.5,-0.5) T6(-9.5,-0.5) T11(-4.5,-0.5) T12(-3.5,-0.5) T13(-2.5,-0.5) T14(-1.5,-0.5) T15(-0.5,-0.5) T16(0.5,-0.5) T17(1.5,-0.5) T18(2.5,-0.5) T19(3.5,-0.5) T20(4.5,-0.5) T25(9.5,-0.5) T26(10.5,-0.5) T27(11.5,-0.5) T28(12.5,-0.5) T29(13.5,-0.5) T30(14.5,-0.5) U1(-14.5,-1.5) U2(-13.5,-1.5) U3(-12.5,-1.5) U4(-11.5,-1.5) U5(-10.5,-1.5) U6(-9.5,-1.5) U11(-4.5,-1.5) U12(-3.5,-1.5) U13(-2.5,-1.5) U14(-1.5,-1.5) U15(-0.5,-1.5) U16(0.5,-1.5) U17(1.5,-1.5) U18(2.5,-1.5) U19(3.5,-1.5) U20(4.5,-1.5) U25(9.5,-1.5) U26(10.5,-1.5) U27(11.5,-1.5) U28(12.5,-1.5) U29(13.5,-1.5) U30(14.5,-1.5) V1(-14.5,-2.5) V2(-13.5,-2.5) V3(-12.5,-2.5) V4(-11.5,-2.5) V5(-10.5,-2.5) V6(-9.5,-2.5) V11(-4.5,-2.5) V12(-3.5,-2.5) V13(-2.5,-2.5) V14(-1.5,-2.5) V15(-0.5,-2.5) V16(0.5,-2.5) V17(1.5,-2.5) V18(2.5,-2.5) V19(3.5,-2.5) V20(4.5,-2.5) V25(9.5,-2.5) V26(10.5,-2.5) V27(11.5,-2.5) V28(12.5,-2.5) V29(13.5,-2.5) V30(14.5,-2.5) W1(-14.5,-3.5) W2(-13.5,-3.5) W3(-12.5,-3.5) W4(-11.5,-3.5) W5(-10.5,-3.5) W6(-9.5,-3.5) W11(-4.5,-3.5) W12(-3.5,-3.5) W13(-2.5,-3.5) W14(-1.5,-3.5) W15(-0.5,-3.5) W16(0.5,-3.5) W17(1.5,-3.5) W18(2.5,-3.5) W19(3.5,-3.5) W20(4.5,-3.5) W25(9.5,-3.5) W26(10.5,-3.5) W27(11.5,-3.5) W28(12.5,-3.5) W29(13.5,-3.5) W30(14.5,-3.5) Y1(-14.5,-4.5) Y2(-13.5,-4.5) Y3(-12.5,-4.5) Y4(-11.5,-4.5) Y5(-10.5,-4.5) Y6(-9.5,-4.5) Y11(-4.5,-4.5) Y12(-3.5,-4.5) Y13(-2.5,-4.5) Y14(-1.5,-4.5) Y15(-0.5,-4.5) Y16(0.5,-4.5) Y17(1.5,-4.5) Y18(2.5,-4.5) Y19(3.5,-4.5) Y20(4.5,-4.5) Y25(9.5,-4.5) Y26(10.5,-4.5) Y27(11.5,-4.5) Y28(12.5,-4.5) Y29(13.5,-4.5) Y30(14.5,-4.5)
DPAK-A
  rect 1.6x2.997 smd: 1(-2.286,-2.781) 3(2.286,-2.781)
  rect 5.791x6.198 smd: 4(0,4.381)
FI-R51-HF_VF_DUAL
  rect 0.25x1.55 smd: 1(-12.5,2.525) 2(-12,2.525) 3(-11.5,2.525) 4(-11,2.525) 5(-10.5,2.525) 6(-10,2.525) 7(-9.5,2.525) 8(-9,2.525) 9(-8.5,2.525) 10(-8,2.525) 11(-7.5,2.525) 12(-7,2.525) 13(-6.5,2.525) 14(-6,2.525) 15(-5.5,2.525) 16(-5,2.525) 17(-4.5,2.525) 18(-4,2.525) 19(-3.5,2.525) 20(-3,2.525) 21(-2.5,2.525) 22(-2,2.525) 23(-1.5,2.525) 24(-1,2.525) 25(-0.5,2.525) 26(0,2.525) 27(0.5,2.525) 28(1,2.525) 29(1.5,2.525) 30(2,2.525) 31(2.5,2.525) 32(3,2.525) 33(3.5,2.525) 34(4,2.525) 35(4.5,2.525) 36(5,2.525) 37(5.5,2.525) 38(6,2.525) 39(6.5,2.525) 40(7,2.525) 41(7.5,2.525) 42(8,2.525) 43(8.5,2.525) 44(9,2.525) 45(9.5,2.525) 46(10,2.525) 47(10.5,2.525) 48(11,2.525) 49(11.5,2.525) 50(12,2.525) 51(12.5,2.525)
  rect 2.5x1.55 smd: 52(-15.5,2.525) 53(15.5,2.525) 54(-15.5,-2.525) 55(15.5,-2.525)
  rect 1.3x1.55 smd: 56(-12.5,-2.525) 57(-7.5,-2.525) 58(-2.5,-2.525) 59(2.5,-2.525) 60(7.5,-2.525) 61(12.5,-2.525)
  rect 2.05x2.5 smd: 62(18.4,-0.55) 63(-18.4,-0.55)
GT11MSCBE
  rect 3.175x0.762 smd: 1(2.603,2.54) 2(2.603,0) 3(2.603,-2.54) 4(-2.603,2.54) 6(-2.603,-2.54)
HDR1
  rect 1.575x1.575 hole 1.067: 1(0,0)
HDR1X3
  rect 1.575x1.575 hole 1.067: 1(0,0)
  round 1.575 hole 1.067: 2(2.54,0) 3(5.08,0)
HDR1X3_2MM
  rect 1.651x1.651 hole 1.143: 1(0,0)
  round 1.651 hole 1.143: 2(2,0) 3(4,0)
HDR1X4
  rect 1.575x1.575 hole 1.067: 1(0,0)
  round 1.575 hole 1.067: 2(2.54,0) 3(5.08,0) 4(7.62,0)
HDR1X4-B4B-ZR_JST
  rect 1.27x1.27 hole 0.711: 1(0,0)
  round 1.27 hole 0.711: 2(-1.499,0) 3(-2.997,0) 4(-4.496,0)
HDR1X6-B6B-ZR_JST
  rect 1.27x1.27 hole 0.711: 1(0,0)
  round 1.27 hole 0.711: 2(-1.499,0) 3(-2.997,0) 4(-4.496,0) 5(-5.994,0) 6(-7.493,0)
HDR1X7-B7B-ZR_JST
  rect 1.27x1.27 hole 0.711: 1(0,0)
  round 1.27 hole 0.711: 2(-1.499,0) 3(-2.997,0) 4(-4.496,0) 5(-5.994,0) 6(-7.493,0) 7(-8.992,0)
HDR1X12
  rect 1.575x1.575 hole 1.067: 1(0,0)
  round 1.575 hole 1.067: 2(2.54,0) 3(5.08,0) 4(7.62,0) 5(10.16,0) 6(12.7,0) 7(15.24,0) 8(17.78,0) 9(20.32,0) 10(22.86,0) 11(25.4,0) 12(27.94,0)
HDR1X12-B12B-ZR_JST
  rect 1.27x1.27 hole 0.711: 1(0,0)
  round 1.27 hole 0.711: 2(-1.499,0) 3(-2.997,0) 4(-4.496,0) 5(-5.994,0) 6(-7.493,0) 7(-8.992,0) 8(-10.49,0) 9(-11.989,0) 10(-13.487,0) 11(-14.986,0) 12(-16.485,0)
HDR1X14
  rect 1.575x1.575 hole 1.067: 1(0,0)
  round 1.575 hole 1.067: 2(2.54,0) 3(5.08,0) 4(7.62,0) 5(10.16,0) 6(12.7,0) 7(15.24,0) 8(17.78,0) 9(20.32,0) 10(22.86,0) 11(25.4,0) 12(27.94,0) 13(30.48,0) 14(33.02,0)
HDR2_2MM
  rect 1.651x1.651 hole 1.143: 1(0,0)
  round 1.651 hole 1.143: 2(2,0)
HDR2P_1R
  rect 1.778x1.778 hole 1.016: 1(0,0)
  round 1.778 hole 1.016: 2(0,2.54)
HDR2X5
  rect 1.575x1.575 hole 1.067: 1(0,0)
  round 1.575 hole 1.067: 2(0,2.54) 3(2.54,0) 4(2.54,2.54) 5(5.08,0) 6(5.08,2.54) 7(7.62,0) 8(7.62,2.54) 9(10.16,0) 10(10.16,2.54)
HDR7X2-5103308_TYCO
  round 1.651 hole 1.067: 1(0,0) 2(2.54,0) 3(0,-2.54) 4(2.54,-2.54) 5(0,-5.08) 6(2.54,-5.08) 7(0,-7.62) 8(2.54,-7.62) 9(0,-10.16) 10(2.54,-10.16) 11(0,-12.7) 12(2.54,-12.7) 13(0,-15.24) 14(2.54,-15.24)
HDR10X2-5103308_TYCO
  round 1.651 hole 1.067: 1(0,0) 2(2.54,0) 3(0,-2.54) 4(2.54,-2.54) 5(0,-5.08) 6(2.54,-5.08) 7(0,-7.62) 8(2.54,-7.62) 9(0,-10.16) 10(2.54,-10.16) 11(0,-12.7) 12(2.54,-12.7) 13(0,-15.24) 14(2.54,-15.24) 15(0,-17.78) 16(2.54,-17.78) 17(0,-20.32) 18(2.54,-20.32) 19(0,-22.86) 20(2.54,-22.86)
HDR-2X3-A-RA
  rect 1.778x1.778 hole 1.27: 1(0,0)
  round 1.778 hole 1.27: 2(0,-2.54) 3(-2.54,0) 4(-2.54,-2.54) 5(-5.08,0) 6(-5.08,-2.54)
HTP-48RD28
  round 1.219 hole 0.711: 1(0,0)
IHLP3232DZER
  rect 2.413x5.334 smd: 1(-3.607,0) 2(3.607,0)
IND2-74404063330_WURTH
  rect 5.588x1.803 smd: 1(0,2.311) 2(0,-2.311)
IND-CDRH104R_SUMIDA
  rect 3.302x2.032 smd: 1(0,4.623) 2(0,-4.623)
IND-SRN4018_BOURNS
  rect 1.499x3.607 smd: 1(-1.524,0) 2(1.524,0)
IND-SRN6045TA_BOURNS
  rect 5.2x2.36 smd: 1(0,2.083) 2(0,-2.083)
IND-SRR1005_BOURNS
  rect 2.997x2.794 smd: 1(5.144,0) 2(-5.144,0)
IR3-TSOP34_VIS
  round 2.032 hole 1.27: 1(2.54,0) 2(0,0) 3(-2.54,0)
JACK-PJ-002AH_CUI
  oval 1.778x4.318 hole 1.016x3.556: 1(0,0)
  oval 1.778x3.8 hole 1.016x3: 2(6,0)
  oval 3.8x1.778 hole 3x1.016: 3(3,4.7)
JST_B2B-EH
  rect 1.575x1.575 hole 1.067: 1(0,0)
  round 1.575 hole 1.067: 2(2.489,0)
JST_B10B-ZR
  round 1.27 hole 0.711: 1(0,-6.75) 2(0,-5.25) 3(0,-3.75) 4(0,-2.25) 5(0,-0.75) 6(0,0.75) 7(0,2.25) 8(0,3.75) 9(0,5.25) 10(0,6.75)
LED-1206
  rect 1.575x1.626 smd: 1(-1.714,0) 2(1.714,0)
LED-LTST-C190_LITEON
  rect 0.787x0.787 smd: 1(-0.7,0) 2(0.8,0)
MOLEX_0475901001
  rect 1.9x2.9 smd: (0,0)
  rect 1.351x0.401 smd: 1(2.675,-1.3) 2(2.675,-0.65) 3(2.675,0) 4(2.675,0.65) 5(2.675,1.3)
  rect 1.9x1.4 hole 1.5x0.83: 6(0,-4.09) 7(0,4.09)
  oval 1.25x1.049 hole 0.851x0.65: 8(3,-2.25) 9(3,2.25)
MOLEX_5034801200_2GPADS
  rect 0.3x0.7 smd: 1(-2.75,0) 2(-2.25,0) 3(-1.75,0) 4(-1.25,0) 5(-0.75,0) 6(-0.25,0) 7(0.25,0) 8(0.75,0) 9(1.25,0) 10(1.75,0) 11(2.25,0) 12(2.75,0)
  rect 0.3x1 smd: 13(-3.54,-2.65) 14(3.54,-2.65)
OSC4-KC2520B_KYO
  rect 1.041x1.092 smd: 1(-0.725,0.925) 2(-0.725,-0.925) 3(0.725,-0.925) 4(0.725,0.925)
POT-3314G
  rect 1.321x1.321 smd: 1(-1.156,2.756) 3(1.156,2.756)
  rect 1.981x1.321 smd: 2(0,-2.756)
PQFP80-PN_TI
  rect 0.305x1.575 smd: 1(-4.75,-6.706) 2(-4.249,-6.706) 3(-3.749,-6.706) 4(-3.251,-6.706) 5(-2.751,-6.706) 6(-2.25,-6.706) 7(-1.75,-6.706) 8(-1.25,-6.706) 9(-0.749,-6.706) 10(-0.249,-6.706) 11(0.249,-6.706) 12(0.749,-6.706) 13(1.25,-6.706) 14(1.75,-6.706) 15(2.25,-6.706) 16(2.751,-6.706) 17(3.251,-6.706) 18(3.749,-6.706) 19(4.249,-6.706) 20(4.75,-6.706) 41(4.75,6.706) 42(4.249,6.706) 43(3.749,6.706) 44(3.251,6.706) 45(2.751,6.706) 46(2.25,6.706) 47(1.75,6.706) 48(1.25,6.706) 49(0.749,6.706) 50(0.249,6.706) 51(-0.249,6.706) 52(-0.749,6.706) 53(-1.25,6.706) 54(-1.75,6.706) 55(-2.25,6.706) 56(-2.751,6.706) 57(-3.251,6.706) 58(-3.749,6.706) 59(-4.249,6.706) 60(-4.75,6.706)
  rect 1.575x0.305 smd: 21(6.706,-4.75) 22(6.706,-4.249) 23(6.706,-3.749) 24(6.706,-3.251) 25(6.706,-2.751) 26(6.706,-2.25) 27(6.706,-1.75) 28(6.706,-1.25) 29(6.706,-0.749) 30(6.706,-0.249) 31(6.706,0.249) 32(6.706,0.749) 33(6.706,1.25) 34(6.706,1.75) 35(6.706,2.25) 36(6.706,2.751) 37(6.706,3.251) 38(6.706,3.749) 39(6.706,4.249) 40(6.706,4.75) 61(-6.706,4.75) 62(-6.706,4.249) 63(-6.706,3.749) 64(-6.706,3.251) 65(-6.706,2.751) 66(-6.706,2.25) 67(-6.706,1.75) 68(-6.706,1.25) 69(-6.706,0.749) 70(-6.706,0.249) 71(-6.706,-0.249) 72(-6.706,-0.749) 73(-6.706,-1.25) 74(-6.706,-1.75) 75(-6.706,-2.25) 76(-6.706,-2.751) 77(-6.706,-3.251) 78(-6.706,-3.749) 79(-6.706,-4.249) 80(-6.706,-4.75)
QF48_PPAD-A
  rect 1.524x0.254 smd: 1(-4.445,2.752) 2(-4.445,2.252) 3(-4.445,1.751) 4(-4.445,1.251) 5(-4.445,0.751) 6(-4.445,0.25) 7(-4.445,-0.25) 8(-4.445,-0.751) 9(-4.445,-1.251) 10(-4.445,-1.751) 11(-4.445,-2.252) 12(-4.445,-2.752) 25(4.445,-2.752) 26(4.445,-2.252) 27(4.445,-1.751) 28(4.445,-1.251) 29(4.445,-0.751) 30(4.445,-0.25) 31(4.445,0.25) 32(4.445,0.751) 33(4.445,1.251) 34(4.445,1.751) 35(4.445,2.252) 36(4.445,2.752)
  rect 0.254x1.524 smd: 13(-2.752,-4.445) 14(-2.252,-4.445) 15(-1.751,-4.445) 16(-1.251,-4.445) 17(-0.751,-4.445) 18(-0.25,-4.445) 19(0.25,-4.445) 20(0.751,-4.445) 21(1.251,-4.445) 22(1.751,-4.445) 23(2.252,-4.445) 24(2.752,-4.445) 37(2.752,4.445) 38(2.252,4.445) 39(1.751,4.445) 40(1.251,4.445) 41(0.751,4.445) 42(0.25,4.445) 43(-0.25,4.445) 44(-0.751,4.445) 45(-1.251,4.445) 46(-1.751,4.445) 47(-2.252,4.445) 48(-2.752,4.445)
  rect 5.08x5.08 smd: 49(0,0)
QFN32-5X5-A_CYP
  rect 0.889x0.305 smd: 1(-2.545,1.75) 2(-2.545,1.25) 3(-2.545,0.75) 4(-2.545,0.25) 5(-2.545,-0.25) 6(-2.545,-0.75) 7(-2.545,-1.25) 8(-2.545,-1.75) 17(2.545,-1.75) 18(2.545,-1.25) 19(2.545,-0.75) 20(2.545,-0.25) 21(2.545,0.25) 22(2.545,0.75) 23(2.545,1.25) 24(2.545,1.75)
  rect 0.305x0.889 smd: 9(-1.75,-2.545) 10(-1.25,-2.545) 11(-0.75,-2.545) 12(-0.25,-2.545) 13(0.25,-2.545) 14(0.75,-2.545) 15(1.25,-2.545) 16(1.75,-2.545) 25(1.75,2.545) 26(1.25,2.545) 27(0.75,2.545) 28(0.25,2.545) 29(-0.25,2.545) 30(-0.75,2.545) 31(-1.25,2.545) 32(-1.75,2.545)
  rect 3.505x3.505 smd: 33(0,0)
SIT1602BC-13-2520_CTS_SITIME
  rect 1.041x1.092 smd: 1(-0.75,0.95) 2(-0.75,-0.95) 3(0.75,-0.95) 4(0.75,0.95)
SOIC3-DBZ_TI
  rect 0.61x1.27 smd: 1(0.95,1.1) 2(-0.95,1.1) 3(0,-1.1)
SOIC5-DBV_TI
  rect 1.321x0.61 smd: 1(-1.187,0.95) 2(-1.187,0) 3(-1.187,-0.95) 4(1.187,-0.95) 5(1.187,0.95)
SOIC5-SOT-23_DBV-TI
  rect 0.6x1.05 smd: 1(-0.95,-1.35) 2(0,-1.35) 3(0.95,-1.35) 4(0.95,1.35) 5(-0.95,1.35)
SOIC6-DRY_TI
  rect 0.305x0.762 smd: 1(-0.5,-0.506) 2(0,-0.506) 3(0.5,-0.506) 4(0.513,0.506) 5(0.013,0.506) 6(-0.487,0.506)
SOIC8
  rect 0.635x2.032 smd: 1(-1.905,-2.489) 2(-0.635,-2.489) 3(0.635,-2.489) 4(1.905,-2.489) 5(1.905,2.489) 6(0.635,2.489) 7(-0.635,2.489) 8(-1.905,2.489)
SOIC8-D_TI
  rect 0.635x2.032 smd: 1(-1.905,-2.489) 2(-0.635,-2.489) 3(0.635,-2.489) 4(1.905,-2.489) 5(1.905,2.489) 6(0.635,2.489) 7(-0.635,2.489) 8(-1.905,2.489)
SOIC8-DDA-A_TI
  rect 0.6x2.2 smd: 1(-1.905,-2.875) 2(-0.635,-2.875) 3(0.635,-2.875) 4(1.905,-2.875) 5(1.905,2.875) 6(0.635,2.875) 7(-0.635,2.875) 8(-1.905,2.875)
  rect 3.099x2.413 smd: 9(0,0)
SOIC8-DGK_TI
  rect 0.356x1.524 smd: 1(-0.975,-2.173) 2(-0.325,-2.173) 3(0.325,-2.173) 4(0.975,-2.173) 5(0.975,2.173) 6(0.325,2.173) 7(-0.325,2.173) 8(-0.975,2.173)
SOIC8-PW_TI
  rect 0.356x1.524 smd: 1(-0.975,-2.96) 2(-0.325,-2.96) 3(0.325,-2.96) 4(0.975,-2.96) 5(0.975,2.96) 6(0.325,2.96) 7(-0.325,2.96) 8(-0.975,2.96)
SOIC8-Q5_TI
  rect 1.524x0.635 smd: 1(-2.667,1.905) 2(-2.667,0.635) 3(-2.667,-0.635) 4(-2.667,-1.905) 5(2.667,-1.905) 6(2.667,-0.635) 7(2.667,0.635) 8(2.667,1.905)
SOIC10-DRC_TI
  rect 0.889x0.305 smd: 1(-1.503,1) 2(-1.503,0.5) 3(-1.503,0) 4(-1.503,-0.5) 5(-1.503,-1) 6(1.503,-1) 7(1.503,-0.5) 8(1.503,0) 9(1.503,0.5) 10(1.503,1)
  rect 1.651x3.15 smd: 11(0,0)
SOIC16-PW_TI
  rect 0.356x1.524 smd: 1(-2.275,-2.96) 2(-1.625,-2.96) 3(-0.975,-2.96) 4(-0.325,-2.96) 5(0.325,-2.96) 6(0.975,-2.96) 7(1.625,-2.96) 8(2.275,-2.96) 9(2.275,2.96) 10(1.625,2.96) 11(0.975,2.96) 12(0.325,2.96) 13(-0.325,2.96) 14(-0.975,2.96) 15(-1.625,2.96) 16(-2.275,2.96)
SOIC24-PW_TI
  rect 0.356x1.524 smd: 1(-3.575,-2.96) 2(-2.925,-2.96) 3(-2.275,-2.96) 4(-1.625,-2.96) 5(-0.975,-2.96) 6(-0.325,-2.96) 7(0.325,-2.96) 8(0.975,-2.96) 9(1.625,-2.96) 10(2.275,-2.96) 11(2.925,-2.96) 12(3.575,-2.96) 13(3.575,2.96) 14(2.925,2.96) 15(2.275,2.96) 16(1.625,2.96) 17(0.975,2.96) 18(0.325,2.96) 19(-0.325,2.96) 20(-0.975,2.96) 21(-1.625,2.96) 22(-2.275,2.96) 23(-2.925,2.96) 24(-3.575,2.96)
SOIC48-DGG_TI
  rect 0.305x1.778 smd: 1(-5.75,-3.708) 2(-5.25,-3.708) 3(-4.75,-3.708) 4(-4.25,-3.708) 5(-3.75,-3.708) 6(-3.25,-3.708) 7(-2.75,-3.708) 8(-2.25,-3.708) 9(-1.75,-3.708) 10(-1.25,-3.708) 11(-0.75,-3.708) 12(-0.25,-3.708) 13(0.25,-3.708) 14(0.75,-3.708) 15(1.25,-3.708) 16(1.75,-3.708) 17(2.25,-3.708) 18(2.75,-3.708) 19(3.25,-3.708) 20(3.75,-3.708) 21(4.25,-3.708) 22(4.75,-3.708) 23(5.25,-3.708) 24(5.75,-3.708) 25(5.75,3.708) 26(5.25,3.708) 27(4.75,3.708) 28(4.25,3.708) 29(3.75,3.708) 30(3.25,3.708) 31(2.75,3.708) 32(2.25,3.708) 33(1.75,3.708) 34(1.25,3.708) 35(0.75,3.708) 36(0.25,3.708) 37(-0.25,3.708) 38(-0.75,3.708) 39(-1.25,3.708) 40(-1.75,3.708) 41(-2.25,3.708) 42(-2.75,3.708) 43(-3.25,3.708) 44(-3.75,3.708) 45(-4.25,3.708) 46(-4.75,3.708) 47(-5.25,3.708) 48(-5.75,3.708)
SOIC56-TSOP_SPANSION
  rect 1.524x0.279 smd: 1(-9.75,6.75) 2(-9.75,6.25) 3(-9.75,5.75) 4(-9.75,5.25) 5(-9.75,4.75) 6(-9.75,4.25) 7(-9.75,3.75) 8(-9.75,3.25) 9(-9.75,2.75) 10(-9.75,2.25) 11(-9.75,1.75) 12(-9.75,1.25) 13(-9.75,0.75) 14(-9.75,0.25) 15(-9.75,-0.25) 16(-9.75,-0.75) 17(-9.75,-1.25) 18(-9.75,-1.75) 19(-9.75,-2.25) 20(-9.75,-2.75) 21(-9.75,-3.25) 22(-9.75,-3.75) 23(-9.75,-4.25) 24(-9.75,-4.75) 25(-9.75,-5.25) 26(-9.75,-5.75) 27(-9.75,-6.25) 28(-9.75,-6.75) 29(9.75,-6.75) 30(9.75,-6.25) 31(9.75,-5.75) 32(9.75,-5.25) 33(9.75,-4.75) 34(9.75,-4.25) 35(9.75,-3.75) 36(9.75,-3.25) 37(9.75,-2.75) 38(9.75,-2.25) 39(9.75,-1.75) 40(9.75,-1.25) 41(9.75,-0.75) 42(9.75,-0.25) 43(9.75,0.25) 44(9.75,0.75) 45(9.75,1.25) 46(9.75,1.75) 47(9.75,2.25) 48(9.75,2.75) 49(9.75,3.25) 50(9.75,3.75) 51(9.75,4.25) 52(9.75,4.75) 53(9.75,5.25) 54(9.75,5.75) 55(9.75,6.25) 56(9.75,6.75)
SOT23
  rect 1.295x0.991 smd: 1(-0.889,0.94) 2(-0.889,-0.965) 3(0.889,0)
SOT23-3_DIO-MOD
  rect 1.016x1.372 smd: 1(0.94,1.092) 2(-0.94,1.092) 3(0,-1.092)
SOT23AVX
  rect 1.016x1.372 smd: 1(0.94,1.092) 2(-0.94,1.092) 3(0,-1.092)
SOT223-A
  rect 3.81x2.007 smd: D1(0,3.15)
  rect 1.499x2.007 smd: D2(0,-3.15) G(-2.299,-3.15) S(2.299,-3.15)
SOT323_DIODESINC
  rect 0.762x1.067 smd: 1(0.66,0.94) 2(-0.66,0.94) 3(0,-0.94)
SOT-5_DRL_R-PDSO-N5
  rect 0.305x0.457 smd: 1(-0.5,-0.679) 2(0,-0.679) 3(0.5,-0.679) 4(0.5,0.679) 5(-0.5,0.679)
SOT-23_ON-SEMI
  rect 0.787x0.889 smd: 1(0.94,1.092) 2(-0.94,1.092) 3(0,-1.092)
SOT-323_SC70_ONSEMI_MOD
  rect 0.711x0.864 smd: 1(-0.635,-0.953) 2(0.635,-0.953) 3(0,0.953)
SW5_GT12MSCBE
  rect 3.175x0.762 smd: 1(2.603,2.54) 2(2.603,0) 3(2.603,-2.54) 4(-2.603,2.54) 6(-2.603,-2.54)
TI_DRC0010J_VSON-10
  rect 0.24x0.6 smd: 1(-1,-1.4) 2(-0.5,-1.4) 3(0,-1.4) 4(0.5,-1.4) 5(1,-1.4) 6(1,1.4) 7(0.5,1.4) 8(0,1.4) 9(-0.5,1.4) 10(-1,1.4)
  custom 0.412x0.412 smd: 11(0,0)
TP-30RD12
  round 0.762 hole 0.305: 1(0,0)
TP-48RD28
  round 1.219 hole 0.711: 1(0,0)
TP-60RD40
  round 1.524 hole 1.016: 1(0,0)
TP_KEYSTONE_5011
  round 2.794 hole 1.6: 1(0,0)
TXC_TM3225
  rect 1.4x1.2 smd: 1(-1.1,-0.85) 2(1.1,-0.85) 3(1.1,0.85) 4(-1.1,0.85)
U_5_DCK
  rect 0.432x1.27 smd: 1(0.65,0.775) 2(0,0.775) 3(-0.65,0.775) 4(-0.65,-0.884) 5(0.65,-0.884)
unnamed
  round 1.27 hole 3.429 unplated: (0,0)
unnamed#3
  round 0.762 smd: 1(0,0)
VSSOP-8_DCU
  rect 0.254x1.27 smd: 1(-0.75,-1.473) 2(-0.25,-1.473) 3(0.25,-1.473) 4(0.75,-1.473) 5(0.75,1.473) 6(0.25,1.473) 7(-0.25,1.473) 8(-0.75,1.473)

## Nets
